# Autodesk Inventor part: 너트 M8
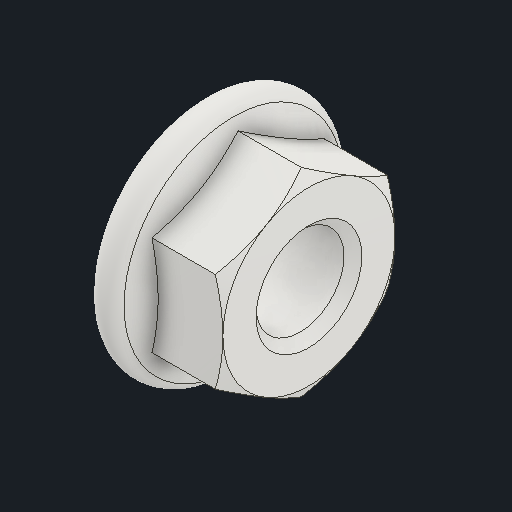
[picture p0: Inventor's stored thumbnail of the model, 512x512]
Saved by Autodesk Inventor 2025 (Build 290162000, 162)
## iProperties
Created: 2025-08
Part Number: 너트 M8
Material: 스테인리스강
Description: 플랜지붙이 6각 너트 - 일반 스레드
Document SubType Name: Modeling
Designer: infra14
Density: 8 g/cm^3
Appearance: 기본값
Author: jhkim
Sending System: Autodesk Inventor 2026
Preprocessor: ST-DEVELOPER v20.1
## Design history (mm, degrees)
feature "Solid1"
node "솔리드1"
